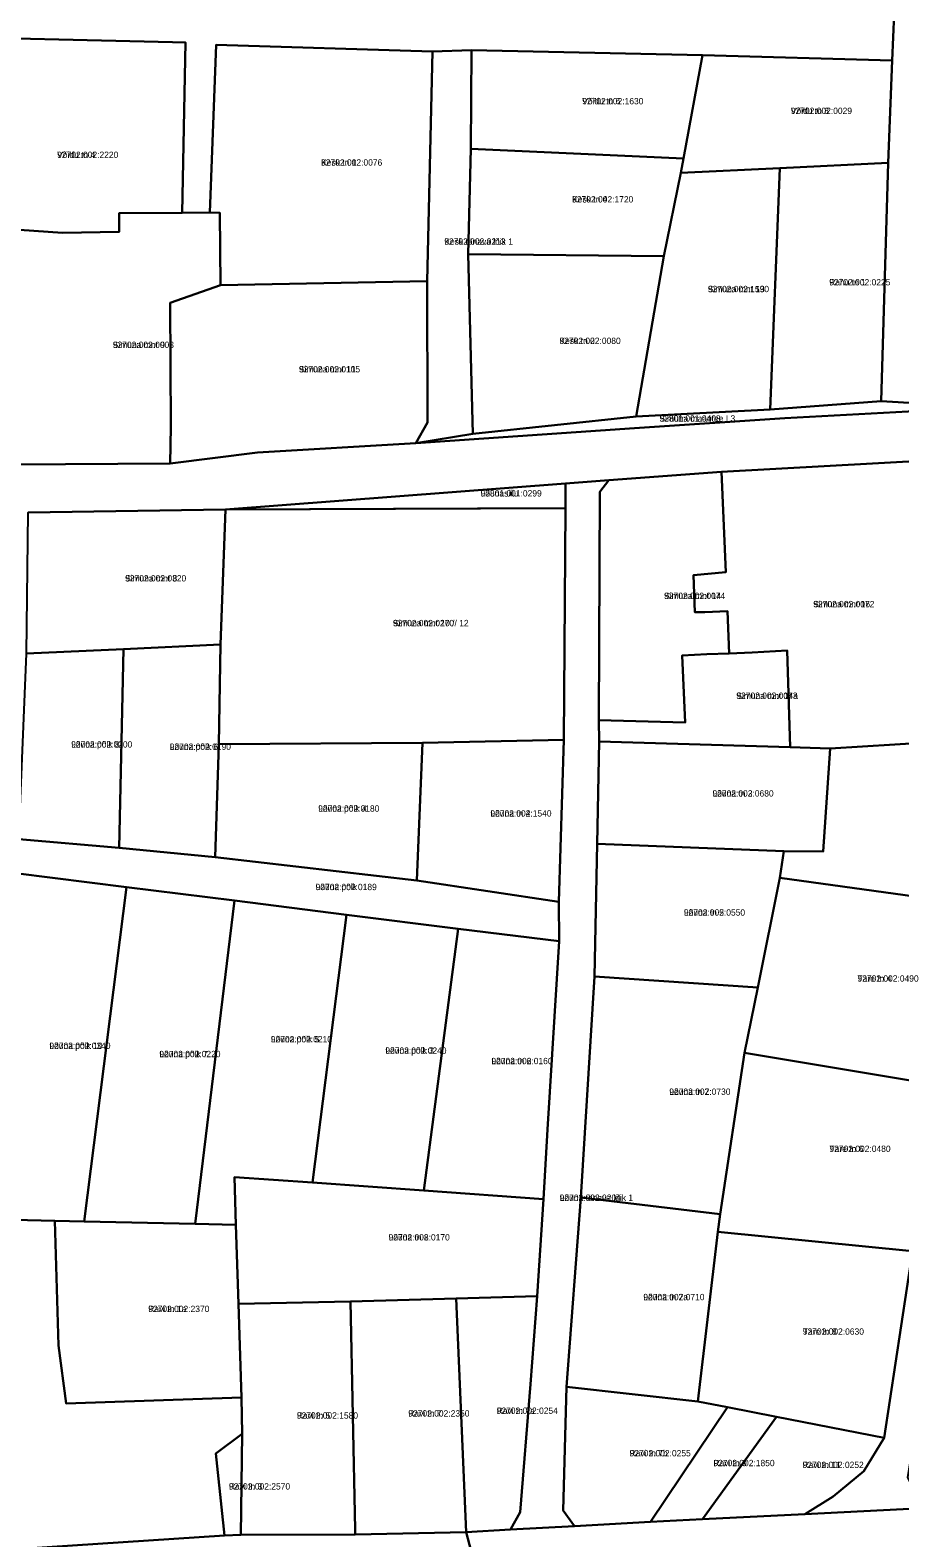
# Model space of a CAD drawing. Extents: x 615668 to 650289, y 6528908 to 6565939.
# Drawn here: x 629055.9 to 629262.1, y 6556457.4 to 6556814.7 of the extents above; entities that cross this region are included whole.
import ezdxf

# ---------------------------------------------------------------- set-up
doc = ezdxf.new("R2010")
doc.units = 0
for name, color, linetype in [('L_AADRESS', 7, 'Continuous'), ('PIIR', 7, 'Continuous'), ('TUNNUS', 7, 'Continuous')]:
    doc.layers.add(name, color=color, linetype=linetype)

msp = doc.modelspace()

# ---------------------------------------------------------------- linework, layer by layer
at = {"layer": 'PIIR'}
for points in [[(629257.62, 6556726.79), (629259.31, 6556783.29), (629260.24, 6556807.52), (629260.76, 6556818.63), (629261.09, 6556843.7), (629261.54, 6556867.52), (629262.22, 6556894.6), (629274.17, 6556903.77), (629272.86, 6556873.44), (629270.58, 6556834.42), (629268.99, 6556771.74), (629266.95, 6556726.26)], [(628990.7, 6556824.99), (629069.35, 6556822.66), (629094.9, 6556822.35), (629147.96, 6556820.93), (629149.97, 6556820.87), (629161.2, 6556821.37), (629210.54, 6556820.35), (629260.76, 6556818.63), (629260.24, 6556807.52), (629215.26, 6556808.83), (629160.51, 6556810.04), (629151.27, 6556809.7), (629099.99, 6556811.28), (629098.46, 6556771.49), (629091.95, 6556771.47), (629092.72, 6556811.8), (629089.65, 6556811.87), (629028.97, 6556813.29), (628986.27, 6556815.13)], [(629050.33, 6556756.26), (629024.87, 6556755.64), (629024.67, 6556765.46), (629026.16, 6556781.98), (629032.14, 6556781.48), (629032.64, 6556787.49), (629026.7, 6556788.01), (629028.97, 6556813.29), (629089.65, 6556811.87), (629092.72, 6556811.8), (629091.95, 6556771.47), (629077.02, 6556771.39), (629077.03, 6556766.92), (629063.55, 6556766.72), (629049.93, 6556767.65)], [(629099.99, 6556811.28), (629151.27, 6556809.7), (629150.01, 6556755.24), (629101.04, 6556754.3), (629100.84, 6556771.46), (629098.46, 6556771.49)], [(629160.51, 6556810.04), (629160.38, 6556786.65), (629159.7, 6556761.63), (629160.86, 6556719.1), (629147.3, 6556716.84), (629150.07, 6556721.71), (629150.01, 6556755.24), (629151.27, 6556809.7)], [(629160.51, 6556810.04), (629215.26, 6556808.83), (629210.78, 6556784.3), (629160.38, 6556786.65)], [(629210.18, 6556780.92), (629210.78, 6556784.3), (629215.26, 6556808.83), (629260.24, 6556807.52), (629259.31, 6556783.29), (629233.58, 6556782.05)], [(629160.38, 6556786.65), (629210.78, 6556784.3), (629210.18, 6556780.92), (629206.08, 6556761.14), (629159.7, 6556761.63)], [(629233.58, 6556782.05), (629259.31, 6556783.29), (629257.62, 6556726.79), (629231.34, 6556724.8)], [(629210.18, 6556780.92), (629233.58, 6556782.05), (629231.34, 6556724.8), (629199.53, 6556723.17), (629206.08, 6556761.14)], [(629049.93, 6556767.65), (629063.55, 6556766.72), (629077.03, 6556766.92), (629077.02, 6556771.39), (629091.95, 6556771.47), (629098.46, 6556771.49), (629100.84, 6556771.46), (629101.04, 6556754.3), (629089.11, 6556750.1), (629089.22, 6556720.71), (629089.09, 6556712.01), (629051.88, 6556711.79), (629050.33, 6556756.26)], [(629159.7, 6556761.63), (629206.08, 6556761.14), (629199.53, 6556723.17), (629160.86, 6556719.1)], [(629101.04, 6556754.3), (629150.01, 6556755.24), (629150.07, 6556721.71), (629147.3, 6556716.84), (629109.82, 6556714.62), (629089.09, 6556712.01), (629089.22, 6556720.71), (629089.11, 6556750.1)], [(629199.53, 6556723.17), (629231.34, 6556724.8), (629257.62, 6556726.79), (629266.99, 6556726.25), (629293.08, 6556727.07), (629292.98, 6556725.27), (629266.95, 6556724.49), (629234.84, 6556722.81), (629199.19, 6556720.4), (629163.44, 6556717.95), (629147.3, 6556716.84), (629160.86, 6556719.1)], [(629213.16, 6556685.6), (629220.8, 6556686.3), (629219.8, 6556710.09), (629269.91, 6556712.83), (629269.5, 6556658.04), (629268.54, 6556645.86), (629245.53, 6556644.51), (629236.05, 6556644.81), (629235.36, 6556667.67), (629227.08, 6556667.24), (629221.62, 6556667.03), (629221.21, 6556677.04), (629215.85, 6556676.82), (629213.45, 6556676.76)], [(629302.25, 6556712.36), (629293.03, 6556650.21), (629292.16, 6556641.97), (629289.91, 6556632.18), (629282.15, 6556583.34), (629274.44, 6556534.82), (629272.44, 6556525.12), (629263.88, 6556471.66), (629267.52, 6556464.44), (629239.55, 6556463.01), (629246.26, 6556467.17), (629253.54, 6556473.18), (629258.39, 6556481.11), (629265.11, 6556525.34), (629271.74, 6556564.58), (629278.15, 6556607.63), (629285.33, 6556655.57), (629291.1, 6556698), (629291.33, 6556706.21), (629289.37, 6556710.26), (629286.13, 6556713.15), (629295.96, 6556713.33), (629295.75, 6556711.83)], [(629193.08, 6556708.07), (629190.93, 6556705.35), (629190.73, 6556651.19), (629190.79, 6556646.15), (629190.31, 6556621.86), (629189.65, 6556590.41), (629186.48, 6556538.04), (629183.07, 6556493.17), (629182.25, 6556463.86), (629184.92, 6556460.18), (629169.78, 6556459.33), (629172.08, 6556463.48), (629174.52, 6556493.81), (629176.12, 6556514.63), (629177.6, 6556537.67), (629178.54, 6556554.18), (629181.27, 6556598.81), (629181.23, 6556608.1), (629182.43, 6556646.54), (629182.81, 6556701.43), (629182.83, 6556707.3)], [(629190.73, 6556651.19), (629190.93, 6556705.35), (629193.08, 6556708.07), (629219.8, 6556710.09), (629220.8, 6556686.3), (629213.16, 6556685.6), (629213.45, 6556676.76), (629215.85, 6556676.82), (629221.21, 6556677.04), (629221.62, 6556667.03), (629216.3, 6556666.81), (629210.44, 6556666.55), (629211.14, 6556650.64)], [(629182.83, 6556707.3), (629182.81, 6556701.43), (629161.96, 6556701.35), (629102.2, 6556701.13)], [(629055.02, 6556667.02), (629055.4, 6556700.38), (629102.2, 6556701.13), (629101.01, 6556669.13), (629078.04, 6556668.04)], [(629101.01, 6556669.13), (629102.2, 6556701.13), (629182.81, 6556701.43), (629182.43, 6556646.54), (629148.87, 6556645.8), (629100.65, 6556645.48)], [(629101.01, 6556669.13), (629100.65, 6556645.48), (629099.78, 6556618.68), (629076.98, 6556620.92), (629078.04, 6556668.04)], [(629055.02, 6556667.02), (629078.04, 6556668.04), (629076.98, 6556620.92), (629053.17, 6556623)], [(629210.44, 6556666.55), (629216.3, 6556666.81), (629221.62, 6556667.03), (629227.08, 6556667.24), (629235.36, 6556667.67), (629236.05, 6556644.81), (629190.79, 6556646.15), (629190.73, 6556651.19), (629211.14, 6556650.64)], [(629245.53, 6556644.51), (629268.54, 6556645.86), (629269.5, 6556658.04), (629273.04, 6556657.52), (629285.33, 6556655.57), (629278.15, 6556607.63), (629233.62, 6556613.85), (629234.55, 6556620.15), (629243.9, 6556620.04)], [(629100.65, 6556645.48), (629148.87, 6556645.8), (629147.57, 6556613.19), (629099.78, 6556618.68)], [(629148.87, 6556645.8), (629182.43, 6556646.54), (629181.23, 6556608.1), (629147.57, 6556613.19)], [(629190.79, 6556646.15), (629236.05, 6556644.81), (629245.53, 6556644.51), (629243.9, 6556620.04), (629234.55, 6556620.15), (629190.31, 6556621.86)], [(629053.17, 6556623), (629076.98, 6556620.92), (629099.78, 6556618.68), (629147.57, 6556613.19), (629181.23, 6556608.1), (629181.27, 6556598.81), (629157.38, 6556601.71), (629130.88, 6556605.06), (629104.32, 6556608.43), (629078.77, 6556611.61), (629052.41, 6556614.95)], [(629190.31, 6556621.86), (629234.55, 6556620.15), (629233.62, 6556613.85), (629228.37, 6556587.86), (629189.65, 6556590.41)], [(629051.06, 6556606.29), (629052.41, 6556614.95), (629078.77, 6556611.61), (629068.73, 6556532.39), (629061.77, 6556532.55), (629042.13, 6556533.01)], [(629078.77, 6556611.61), (629104.32, 6556608.43), (629095.02, 6556531.79), (629068.73, 6556532.39)], [(629228.37, 6556587.86), (629233.62, 6556613.85), (629278.15, 6556607.63), (629271.74, 6556564.58), (629225.23, 6556572.36)], [(629104.65, 6556531.57), (629095.02, 6556531.79), (629104.32, 6556608.43), (629130.88, 6556605.06), (629122.82, 6556541.58), (629104.3, 6556542.9)], [(629130.88, 6556605.06), (629157.38, 6556601.71), (629149.21, 6556539.7), (629122.82, 6556541.58)], [(629181.27, 6556598.81), (629178.54, 6556554.18), (629177.6, 6556537.67), (629149.21, 6556539.7), (629157.38, 6556601.71)], [(629189.65, 6556590.41), (629228.37, 6556587.86), (629225.23, 6556572.36), (629219.45, 6556534.08), (629186.48, 6556538.04)], [(629265.11, 6556525.34), (629218.95, 6556529.93), (629219.45, 6556534.08), (629225.23, 6556572.36), (629271.74, 6556564.58)], [(628977.18, 6556547.6), (628992.33, 6556545.83), (628991, 6556534.18), (629042.13, 6556533.01), (629061.77, 6556532.55), (629062.65, 6556502.94), (629064.44, 6556489.23), (629106.03, 6556490.63), (629106.16, 6556482), (629099.89, 6556477.37), (629100.37, 6556472.9), (629101.99, 6556457.91), (628945.73, 6556447.62), (628954.39, 6556469.23), (628955.28, 6556475.37), (628957.85, 6556491.22), (628965.32, 6556490.06), (628974.42, 6556511.96)], [(629105.27, 6556512.83), (629104.65, 6556531.57), (629104.3, 6556542.9), (629122.82, 6556541.58), (629149.21, 6556539.7), (629177.6, 6556537.67), (629176.12, 6556514.63), (629156.89, 6556514.11), (629131.85, 6556513.38)], [(629186.48, 6556538.04), (629219.45, 6556534.08), (629218.95, 6556529.93), (629214.14, 6556489.71), (629183.07, 6556493.17)], [(629062.65, 6556502.94), (629061.77, 6556532.55), (629068.73, 6556532.39), (629095.02, 6556531.79), (629104.65, 6556531.57), (629105.27, 6556512.83), (629106.03, 6556490.63), (629064.44, 6556489.23)], [(629221.25, 6556488.33), (629214.14, 6556489.71), (629218.95, 6556529.93), (629265.11, 6556525.34), (629258.39, 6556481.11), (629232.8, 6556486.08)], [(629106.16, 6556482), (629106.03, 6556490.63), (629105.27, 6556512.83), (629131.85, 6556513.38), (629132.91, 6556459.36), (629132.98, 6556458.19), (629105.81, 6556458.08)], [(629132.91, 6556459.36), (629131.85, 6556513.38), (629156.89, 6556514.11), (629159.22, 6556458.75), (629132.98, 6556458.19)], [(629176.12, 6556514.63), (629174.52, 6556493.81), (629172.08, 6556463.48), (629169.78, 6556459.33), (629159.22, 6556458.75), (629156.89, 6556514.11)], [(629221.25, 6556488.33), (629202.95, 6556461.18), (629184.92, 6556460.18), (629182.25, 6556463.86), (629183.07, 6556493.17), (629214.14, 6556489.71)], [(629202.95, 6556461.18), (629221.25, 6556488.33), (629232.8, 6556486.08), (629215.25, 6556461.77)], [(629258.39, 6556481.11), (629253.54, 6556473.18), (629246.26, 6556467.17), (629239.55, 6556463.01), (629215.25, 6556461.77), (629232.8, 6556486.08)], [(629100.37, 6556472.9), (629099.89, 6556477.37), (629106.16, 6556482), (629105.81, 6556458.08), (629101.99, 6556457.91)], [(628895.84, 6556455.25), (628898.67, 6556448.49), (628902.76, 6556445.89), (628907.29, 6556445.11), (628945.73, 6556447.62), (629101.99, 6556457.91), (629105.81, 6556458.08), (629132.98, 6556458.19), (629159.22, 6556458.75), (629161.65, 6556449.69), (629146.3, 6556450.15), (629018.02, 6556442.15), (629000.76, 6556441.14), (628923.03, 6556433.48), (628874.04, 6556428.87), (628885.62, 6556439.53)]]:
    msp.add_lwpolyline(points, close=True, dxfattribs=at)
for points in [[(629051.88, 6556711.79), (629089.09, 6556712.01), (629109.82, 6556714.62), (629147.3, 6556716.84), (629163.44, 6556717.95), (629199.19, 6556720.4), (629234.84, 6556722.81), (629266.95, 6556724.49), (629292.98, 6556725.27), (629293.08, 6556727.07), (629322.1, 6556727.8), (629470.66, 6556709.09), (629576.54, 6556678.4), (629618.02, 6556664.89)], [(629627.12, 6556646.24), (629542.64, 6556674.23), (629513.43, 6556683.06), (629492.92, 6556688.41), (629468.19, 6556694.23), (629436.63, 6556700.08), (629390.34, 6556706.29), (629383.07, 6556707.33), (629302.25, 6556712.36), (629295.75, 6556711.83), (629295.96, 6556713.33), (629286.13, 6556713.15), (629269.91, 6556712.83), (629219.8, 6556710.09), (629193.08, 6556708.07), (629182.83, 6556707.3), (629102.2, 6556701.13), (629055.4, 6556700.38)], [(629161.65, 6556449.69), (629159.22, 6556458.75), (629169.78, 6556459.33), (629184.92, 6556460.18), (629202.95, 6556461.18), (629215.25, 6556461.77), (629239.55, 6556463.01), (629267.52, 6556464.44), (629298.85, 6556460.21), (629328.74, 6556456.16)]]:
    msp.add_lwpolyline(points, dxfattribs=at)

# ---------------------------------------------------------------- texts
at = {"layer": 'L_AADRESS'}
for s, p in [('Võidu tn 6', (629186.78, 6556797.17)), ('Võidu tn 8', (629236.23, 6556794.88)), ('Võidu tn 4', (629062.29, 6556784.46)), ('Kesk tn 1', (629124.87, 6556782.64)), ('Kesk tn 4', (629184.38, 6556773.9)), ('Kesk tänava lõik 1', (629154.08, 6556763.89)), ('Rahu tn 1', (629245.33, 6556754.24)), ('Simuna mnt 13', (629216.55, 6556752.64)), ('Simuna mnt 9', (629075.48, 6556739.41)), ('Kesk tn 2', (629181.39, 6556740.37)), ('Simuna mnt 11', (629119.61, 6556733.62)), ('Simuna maantee L3', (629205.09, 6556721.96)), ('Lõunasiilu', (629162.67, 6556704.21)), ('Simuna mnt 8', (629078.39, 6556684.07)), ('Simuna mnt 14', (629206.17, 6556679.92)), ('Simuna mnt 16', (629241.53, 6556677.96)), ('Simuna mnt 10 // 12', (629141.89, 6556673.46)), ('Simuna mnt 14a', (629223.3, 6556656.24)), ('Lõuna põik 8', (629065.61, 6556644.7)), ('Lõuna põik 6', (629088.99, 6556644.15)), ('Lõuna tn 3', (629217.65, 6556633.09)), ('Lõuna põik 4', (629124.18, 6556629.5)), ('Lõuna tn 4', (629165, 6556628.35)), ('Lõuna põik', (629123.56, 6556610.9)), ('Lõuna tn 5', (629210.88, 6556604.86)), ('Tare tn 4', (629252.03, 6556589.21)), ('Lõuna põik 5', (629112.95, 6556574.81)), ('Lõuna põik 10', (629060.45, 6556573.26)), ('Lõuna põik 7', (629086.52, 6556571.31)), ('Lõuna põik 3', (629140.1, 6556572.12)), ('Lõuna tn 6', (629165.24, 6556569.65)), ('Lõuna tn 7', (629207.42, 6556562.38)), ('Tare tn 6', (629245.38, 6556548.85)), ('Lõuna tänava lõik 1', (629181.43, 6556537.25)), ('Lõuna tn 8', (629140.87, 6556527.86)), ('Lõuna tn 7a', (629201.26, 6556513.7)), ('Ravi tn 1a', (629083.88, 6556510.89)), ('Tare tn 8', (629239.06, 6556505.52)), ('Ravi tn 5', (629119.12, 6556485.63)), ('Ravi tn 7', (629145.54, 6556486.12)), ('Ravi tn 7a', (629166.5, 6556486.76)), ('Ravi tn 7b', (629198, 6556476.68)), ('Ravi tn 9', (629217.88, 6556474.36)), ('Ravi tn 11', (629239.01, 6556473.92)), ('Ravi tn 3', (629103.02, 6556468.82))]:
    msp.add_text(s, height=1.5, dxfattribs=at).set_placement(p)
at = {"layer": 'TUNNUS'}
for s, p in [('92702:002:1630', (629186.78, 6556797.17)), ('92702:002:0029', (629236.23, 6556794.88)), ('92702:002:2220', (629062.29, 6556784.46)), ('92702:002:0076', (629124.87, 6556782.64)), ('92702:002:1720', (629184.38, 6556773.9)), ('92702:002:0213', (629154.08, 6556763.89)), ('92702:002:0225', (629245.33, 6556754.24)), ('92702:002:1590', (629216.55, 6556752.64)), ('92702:002:0003', (629075.48, 6556739.41)), ('92702:002:0080', (629181.39, 6556740.37)), ('92702:002:0105', (629119.61, 6556733.62)), ('92801:001:0408', (629205.09, 6556721.96)), ('92801:001:0299', (629162.67, 6556704.21)), ('92702:002:0320', (629078.39, 6556684.07)), ('92702:002:0074', (629206.17, 6556679.92)), ('92702:002:0072', (629241.53, 6556677.96)), ('92702:002:0270', (629141.89, 6556673.46)), ('92702:002:0073', (629223.3, 6556656.24)), ('92702:002:0200', (629065.61, 6556644.7)), ('92702:002:0190', (629088.99, 6556644.15)), ('92702:002:0680', (629217.65, 6556633.09)), ('92702:002:0180', (629124.18, 6556629.5)), ('92702:002:1540', (629165, 6556628.35)), ('92702:002:0189', (629123.56, 6556610.9)), ('92702:002:0550', (629210.88, 6556604.86)), ('92702:002:0490', (629252.03, 6556589.21)), ('92702:002:0210', (629112.95, 6556574.81)), ('92702:002:0340', (629060.45, 6556573.26)), ('92702:002:0220', (629086.52, 6556571.31)), ('92702:002:0240', (629140.1, 6556572.12)), ('92702:002:0160', (629165.24, 6556569.65)), ('92702:002:0730', (629207.42, 6556562.38)), ('92702:002:0480', (629245.38, 6556548.85)), ('92702:002:0204', (629181.43, 6556537.25)), ('92702:002:0170', (629140.87, 6556527.86)), ('92702:002:0710', (629201.26, 6556513.7)), ('92702:002:2370', (629083.88, 6556510.89)), ('92702:002:0630', (629239.06, 6556505.52)), ('92702:002:1580', (629119.12, 6556485.63)), ('92702:002:2350', (629145.54, 6556486.12)), ('92702:002:0254', (629166.5, 6556486.76)), ('92702:002:0255', (629198, 6556476.68)), ('92702:002:1850', (629217.88, 6556474.36)), ('92702:002:0252', (629239.01, 6556473.92)), ('92702:002:2570', (629103.02, 6556468.82))]:
    msp.add_text(s, height=1.5, dxfattribs=at).set_placement(p)

doc.saveas('drawing.dxf')
